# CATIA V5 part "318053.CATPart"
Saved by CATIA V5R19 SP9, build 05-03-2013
Part number: 318053
Source: Unknown
Bounding box of the stored display mesh (mm): x -693.471 to 180, y 131 to 134, z 193.051 to 591
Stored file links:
  D:\16-SIL\kale oto\R19_V2\318053.CATPart
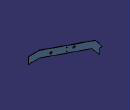
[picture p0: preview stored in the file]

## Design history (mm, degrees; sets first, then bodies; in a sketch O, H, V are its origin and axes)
Body1 "157\\127\\MANIFOLD_SOLID_BREP #80873" (main body)
  Solid1: solid without history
